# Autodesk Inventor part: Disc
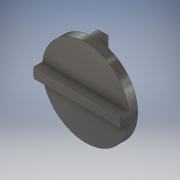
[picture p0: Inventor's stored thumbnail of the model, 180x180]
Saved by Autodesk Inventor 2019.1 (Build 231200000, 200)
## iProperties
Created: 2020-03
Part Number: Disc
Material: Steel, Mild
Document SubType Name: Modeling
Designer: Oghenemarho
Density: 7.85 g/cm^3
Appearance: Steel - Polished
Mass: 840.451 g
Surface Area: 240.461 cm^2
Volume: 107.064 cm^3
Author: Oghenemarho
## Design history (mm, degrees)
sketch "Sketch1"
  geometry: C1 r 50.8 at (0, 0); 1 further point
  constraints: 1 centre point, 1 coincident
  dimensions: "d0" = 101.6 diameter of C1
extrude "Extrusion1" new body sketch "Sketch1" distance "d1" = 10.16; taper "d2" = 0 deg
sketch "Sketch2"
  geometry: L1 (-50.445, 5.994)-(50.445, 5.994); L2 (-50.445, -5.994)-(50.445, -5.994); A1 r 50.8 centre (0, 0) between (-50.445, 5.994) and (50.445, 5.994) reference; 1 further point
  constraints: 4 end point, 4 point on circle, 2 horizontal, 1 parallel
  dimensions: "d3" = 11.9888 distance between parallel lines of L2 L1
extrude "Extrusion2" join sketch "Sketch2" distance "d4" = 10.16; taper "d5" = 0 deg
sketch "Sketch3"
  geometry: L1 (-5.994, 50.445)-(-5.994, -50.445); L2 (5.994, 50.445)-(5.994, -50.445); A1 r 50.8 centre (0, 0) between (-5.994, 50.445) and (-5.994, -50.445) reference; 1 further point
  constraints: 4 end point, 4 point on circle, 2 parallel, 2 vertical
  dimensions: "d6" = 11.9888 distance between parallel lines of L2 L1
extrude "Extrusion3" join sketch "Sketch3" distance "d7" = 10.16; taper "d8" = 0 deg
body "Solid1"
